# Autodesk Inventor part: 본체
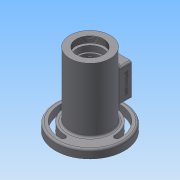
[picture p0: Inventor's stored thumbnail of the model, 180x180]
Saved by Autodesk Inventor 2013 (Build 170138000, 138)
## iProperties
Created: 2017-05
Part Number: 본체
Material: Generic
Document SubType Name: Modeling
Designer: Administrator
Density: 1 g/cm^3
Author: Administrator
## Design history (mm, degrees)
sketch "스케치1"
  geometry: C1 r 31 at (0, 0); 1 further point
  constraints: 1 centre point, 1 coincident
  dimensions: "d0" = 62 diameter of C1
extrude "돌출1" new body sketch "스케치1" stored distance "d2" = 115; taper "d3" = 0 deg
sketch "스케치2"
  geometry: L1 (31, 57.5)-(-31, 57.5) reference; L2 (-31, -57.5)-(31, -57.5) reference; L3 (0, 57.5)-(0, -57.5); L4 (21, 57.5)-(21, 48.5); L5 (21, 48.5)-(24, 48.5); L6 (24, 48.5)-(24, 45.5); L7 (24, 45.5)-(20, 45.5); L8 (20, 45.5)-(20, 36.5); L9 (20, 36.5)-(17.5, 36.5); L10 (17.5, 36.5)-(17.5, 33.25); L11 (17.5, 33.25)-(18.5, 33.25); L12 (18.5, 33.25)-(18.5, 31.5); L13 (18.5, 31.5)-(17.5, 31.5); L14 (17.5, 31.5)-(17.5, 20.5); L15 (17.5, 20.5)-(26, 20.5); L16 (26, 20.5)-(26, -17.5); L17 (12.5, -36.2)-(12.5, -43.5); L18 (16, -43.5)-(22, -57.5); L19 (12.5, -36.2)-(10, -36.2); L20 (10, -36.2)-(10, -33.5); L21 (10, -33.5)-(16.5, -33.5); L22 (16.5, -33.5)-(16.5, -28.5); L23 (16.5, -28.5)-(17.5, -28.5); L24 (17.5, -28.5)-(17.5, -17.5); L25 (17.5, -17.5)-(26, -17.5); L26 (12.5, -39.269)-(12.5, -39.269); L27 (12.5, -43.5)-(16, -43.5); 1 further point
  constraints: 50 end point, 11 perpendicular, 10 parallel, 3 point on line, 2 midpoint, 1 collinear, 1 vertical alignment
  dimensions: "d4" = 42 diameter of L4 L3; "d6" = 48 diameter of L6 L3; "d7" = 40 diameter of L8 L3; "d8" = 44 diameter of L18.end L3; "d10" = 14 vertical distance of L18.start L18.end; "d12" = 20 diameter of L20 L3; "d13" = 33 diameter of L22 L3; "d14" = 35 diameter of L24 L3; "d15" = 52 diameter of L16 L3; "d16" = 35 diameter of L10 L3; "d17" = 37 diameter of L12 L3; "d18" = 12 distance between parallel lines of L7 L1; "d19" = 3 distance of L5.end L6.end; "d20" = 21 distance between parallel lines of L9 L1; "d21" = 26 distance from line of L12.end L1; "d22" = 38 distance of L15.end L16.end; "d23" = 11 distance of L13.end L14.end; "d27" = 32 diameter of L18.start L3; "d28" = 2.7 distance of L19.end L20.end; "d29" = 25 diameter of L17 L3; "d30" = 7.3 distance of L17.start L17.end; "d31" = 1.75 distance of L11.end L12.end
revolve "회전1" sketch "스케치2" stored, may be unused: angle "d32" = 90 deg
node "작업 평면1"
sketch "스케치3"
  geometry: C1 r 53 at (0, 0); C2 r 31 at (0, 0) reference; C3 r 31 at (0, 0); 1 further point
  constraints: 2 centre point, 2 coincident, 1 concentric
  dimensions: "d34" = 106 diameter of C1
extrude "돌출2" join sketch "스케치3" distance "d36" = 13; taper "d37" = 0 deg
sketch "스케치4"
  geometry: C1 r 31 at (0, 0) reference; A1 r 41.5 centre (0, 0) between (-41.5, 0) and (41.5, 0); A2 r 4 centre (-41.5, 0) between (-45.5, 0) and (-37.5, 0); A3 r 4 centre (41.5, 0) between (45.5, 0) and (37.5, 0); A4 r 4 centre (0, 41.5) between (0, 37.5) and (0, 45.5); A5 r 4 centre (0, -41.5) between (0, -37.5) and (0, -45.5); A6 r 37.5 centre (0, 0) between (0, -37.5) and (37.5, 0); A7 r 37.5 centre (0, 0) between (0, 37.5) and (-37.5, 0); A8 r 45.5 centre (0, 0) between (0, -45.5) and (45.5, 0); A9 r 45.5 centre (0, 0) between (0, 45.5) and (-45.5, 0)
  constraints: 20 point on circle, 9 centre point, 5 equal radius, 2 horizontal alignment, 2 vertical alignment
  dimensions: "d38" = 83 diameter of A1; "d42" = 45.5 radius of A9; "d43" = 37.5 radius of A7; "d44" = 8 diameter of A2
extrude "돌출3" cut sketch "스케치4" distance "d45" = 13; taper "d46" = 0 deg
node "작업 평면2"
sketch "스케치5"
  geometry: L1 (20, 26.5)-(20, -23.5); L2 (20, -23.5)-(-20, -23.5); L3 (-20, -23.5)-(-20, 26.5); L4 (-20, 26.5)-(20, 26.5); L5 (20, 26.5)-(-20, -23.5); L6 (20, -23.5)-(-20, 26.5); L7 (31, 57.5)-(-31, 57.5) reference; L8 (31, -41.5)-(31, 57.5) reference; 2 further points
  constraints: 12 end point, 2 midpoint, 2 parallel, 1 perpendicular, 1 vertical
  dimensions: "d48" = 56 distance from line of point (0, 1.5) L7; "d49" = 31 distance from line of point (0, 1.5) L8; "d50" = 50 distance of L2.end L3.end; "d51" = 40 distance of L3.end L1.start
extrude "돌출4" join sketch "스케치5" stored distance "d52" = 13; taper "d53" = 0 deg
sketch "스케치6"
  geometry: L1 (-20, -26.5)-(-20, 23.5) reference; L2 (20, -26.5)-(-20, -26.5) reference; L3 (20, 23.5)-(20, -26.5) reference; L4 (-20, 23.5)-(20, 23.5) reference; L5 (11, 14.5)-(11, -17.5); L6 (11, -17.5)-(-11, -17.5); L7 (-11, -17.5)-(-11, 14.5); L8 (-11, 14.5)-(11, 14.5); 1 further point
  constraints: 8 end point, 3 other
  dimensions: "d54" = 32 distance of L5.start L5.end
extrude "돌출5" cut sketch "스케치6" stored distance "d56" = 13; taper "d57" = 0 deg
sketch "스케치8"
  geometry: L1 (50, 0)-(0, 0) reference; L2 (-31, -13)-(-31, -75) reference; 2 further points
  constraints: 1 other
  dimensions: "d70" = 56 distance from line of point (25, -8) L2; "d71" = 8 distance from line of point (25, -8) L1
feature "엠보싱1" sketch "스케치8" dims "d72" = 0.5, "d73" = 0
feature "스레드1" dims "d74" = 10, "d75" = 0
fillet "모깎기1" dims "d76" = 3
fillet "모깎기2" dims "d77" = 3
fillet "모깎기3" dims "d78" = 3
fillet "모깎기4" dims "d79" = 3
fillet "모깎기5" dims "d80" = 3
fillet "모깎기6" dims "d81" = 3
chamfer "모따기2" distance "d85" = 1; stored, may be unused: second distance "d86" = 2, angle "d87" = 45 deg
fillet "모깎기7" dims "d90" = 3
fillet "모깎기8" dims "d106" = 3
fillet "모깎기9" dims "d122" = 0.3
sketch "스케치13"
  geometry: 5 further points
  constraints: 2 horizontal alignment, 2 vertical alignment
  dimensions: "d126" = 31 distance of point (15.5, 20.5) point (-15.5, 20.5); "d128" = 41 distance of point (-15.5, -20.5) point (-15.5, 20.5); "d129" = 15.5 horizontal distance of point (0, 0) point (-15.5, 20.5); "d130" = 20.5 vertical distance of point (0, 0) point (-15.5, 20.5)
hole "구멍4" sketch "스케치13" at (-15.5, -20.5), (-15.5, 20.5), (15.5, 20.5), (15.5, -20.5) diameter "d131" = 2.459; stored, may be unused: countersink angle "d135" = 90 deg, drill point angle "d137" = 118 deg; dims "d132" = 6, "d133" = 4, "d134" = 2, "d136" = 8
fillet "모깎기10" dims "d138" = 0.3
node "솔리드1"
other parameters: "d33" = -3, "d40" = 91, "d41" = 75, "d47" = 44
